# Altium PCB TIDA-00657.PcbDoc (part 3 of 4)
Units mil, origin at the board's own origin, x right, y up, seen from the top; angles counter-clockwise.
Board outline 2500 x 2500 mil, 4 copper layers (Top Layer, MidLayer1, MidLayer2, Bottom Layer); 149 components, 57 nets, 332 pads, 124 vias.
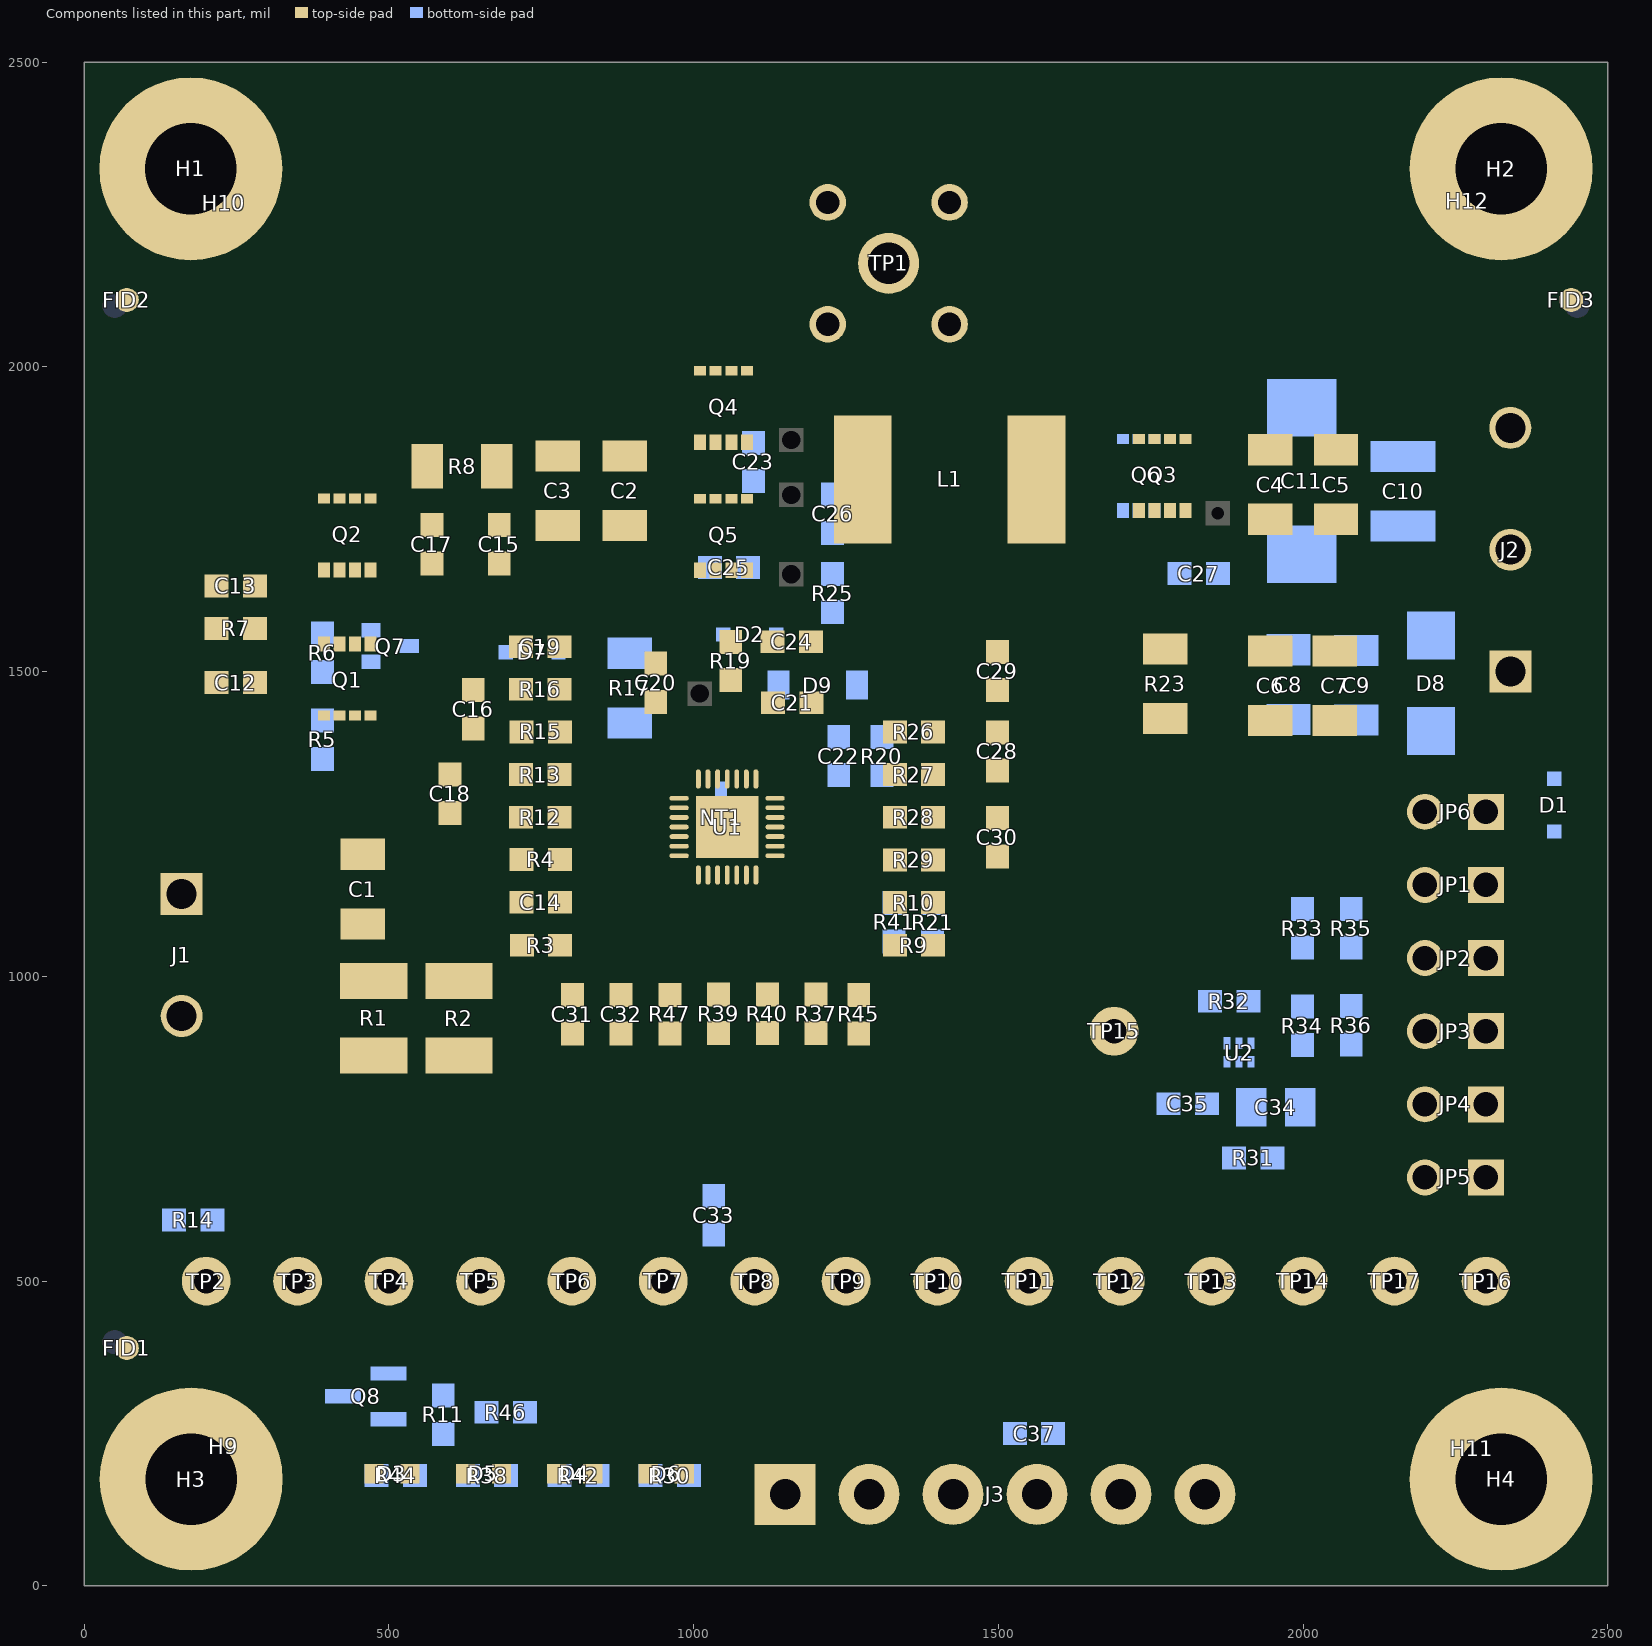
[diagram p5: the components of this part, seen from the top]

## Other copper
Top Layer:
  rectangle net PGND: 265,2148 284,2162
  rectangle net PGND: 283,2159 301,2172
  rectangle net PGND: 295,2156 312,2181
  rectangle net PGND: 278,2150 309,2164
  rectangle net PGND: 250,2140 311,2153
  rectangle net PGND: 312,2183 328,2199
  rectangle net PGND: 321,2181 336,2211
  rectangle net PGND: 332,2183 348,2225
  rectangle net PGND: 348,2234 359,2244
  rectangle net PGND: 352,2231 367,2265
  rectangle net PGND: 341,2160 383,2240
  rectangle net PGND: 305,2125 375,2188
  rectangle net NetC13_1: 454,1610 470,1626
  rectangle net NetC13_1: 443,1606 456,1633
  region net NetC13_1: 361,1570 385,1594 344,1635 320,1611
  region net NetQ1_4: 333,1539 346.5,1552.5 309,1590 295.5,1576.5
  region net BATSRC: 1281,1201 1290,1210 1270,1230 1261,1221
  region net BATSRC: 1275.5,1197.5 1282,1204 1259.5,1226.5 1253,1220
  region net BATSRC: 1279,1182 1287,1190 1247,1230 1239,1222
  region net BATSRC: 1275.5,1173.5 1283,1181 1235.5,1228.5 1228,1221
  region net BATDRV: 1256,1243 1268,1255 1262,1261 1250,1249
  region net BATDRV: 1245,1243 1266,1264 1261,1269 1240,1248
  region net BATDRV: 1237,1243 1267.5,1273.5 1260,1281 1229.5,1250.5
  region net SRN: 1290,1300 1306,1316 1292,1330 1276,1314
  region net SRN: 1272,1302 1305.5,1335.5 1295,1346 1261.5,1312.5
  region net GND: 1387,675 1434.5,722.5 1296,861 1248.5,813.5
  region net GND: 1517.14,751.14 1562,796 1515.86,842.14 1471,797.28
  region net GND: 1475.5,796.5 1556,877 1463.5,969.5 1383,889
  region net CMPOUT: 1350.5,930.5 1358,938 1343.5,952.5 1336,945
  region net CMPOUT: 1307,955 1319,967 1301,985 1289,973
  region net CMPOUT: 1269,991 1279,1001 1267,1013 1257,1003
  region net CMPOUT: 1201,1042 1210,1051 1191,1070 1182,1061
  region net CMPOUT: 1217,1040 1228,1051 1191,1088 1180,1077
  region net CMPOUT: 1154,1148 1160,1154 1153,1161 1147,1155
  region net CMPOUT: 1146.5,1131.5 1161,1146 1139.5,1167.5 1125,1153
  region net CMPOUT: 1241,1033 1264.5,1056.5 1160,1161 1136.5,1137.5
  region net SCL: 1118,997 1153,1032 1125,1060 1090,1025
  region net SCL: 1092,1065 1098.5,1071.5 1092,1078 1085.5,1071.5
  region net SCL: 1104,1038 1118.5,1052.5 1096,1075 1081.5,1060.5
  region net PMON: 986,1026 1008.5,1048.5 998,1059 975.5,1036.5
  region net PMON: 975,1031 1009,1065 998,1076 964,1042
  region net PMON: 952,1032 963,1043 957,1049 946,1038
  region net PMON: 963,1034 1008.5,1079.5 997,1091 951.5,1045.5
  region net IDCHG: 911,1018 929,1036 920,1045 902,1027
  region net IDCHG: 880,1016 893,1029 882,1040 869,1027
  region net IDCHG: 896,1018 957.5,1079.5 938,1099 876.5,1037.5
  region net IDCHG: 950,1077 979,1106 967,1118 938,1089
  region net IDCHG: 939,1081 976.5,1118.5 968,1127 930.5,1089.5
  region net VIN: 364.5,1125.5 377,1138 362.5,1152.5 350,1140
  region net PGND: 385,890 407,912 369,950 347,928
  region net NetC1_2: 410.5,941.5 425,956 405.5,975.5 391,961
  region net NetC1_2: 653,967 687.5,1001.5 574,1115 539.5,1080.5
  region net GND: 675.5,1097.5 710,1132 654.5,1187.5 620,1153
  region net GND: 624,1151 672,1199 620,1251 572,1203
  region net VIN: 570,1137 578.5,1145.5 572,1152 563.5,1143.5
  region net VIN: 557,1137 572,1152 565,1159 550,1144
  region net VIN: 549,1140 565.5,1156.5 551,1171 534.5,1154.5
  region net VIN: 694.5,1049.5 704,1059 683.5,1079.5 674,1070
  region net VIN: 691.28,1027 705.14,1040.86 549,1197 535.14,1183.14
  region net ACDET: 765,1023 778,1036 770,1044 757,1031
  region net ACDET: 722.5,956.5 731,965 718.5,977.5 710,969
  region net ACDET: 728,966 795,1033 783,1045 716,978
  region net IADP: 758,936 819,997 808,1008 747,947
  region net IADP: 827,997 849,1019 837,1031 815,1009
  region net IADP: 815,1002 846,1033 841,1038 810,1007
  region net IADP: 824.14,1025.86 832.28,1034 821.14,1045.14 813,1037
  region net IADP: 834.36,1031.36 836,1033 833.64,1035.36 832,1033.72
  region net IADP: 829,1033 831,1035 818,1048 816,1046
  region net IADP: 830.14,1031.86 959,1160.72 944.86,1174.86 816,1046
  region net ACDET: 798.5,1085.5 820,1107 803.5,1123.5 782,1102
  region net ACDET: 853,1162 858,1167 849,1176 844,1171
  region net ACDET: 852.5,1139.5 877,1164 862.5,1178.5 838,1154
  region net ACDET: 801.5,1063.5 897,1159 878.5,1177.5 783,1082
  region net IADP: 955,1161 979,1185 967,1197 943,1173
  region net ACDET: 892,1159 943,1210 936,1217 885,1166
  region net ACDET: 896,1155 950,1209 944,1215 890,1161
  region net ACOK: 880,1202 901,1223 894,1230 873,1209
  region net ACOK: 879.5,1193.5 911,1225 904.5,1231.5 873,1200
  region net ACDRV: 873,1241 883.5,1251.5 867,1268 856.5,1257.5
  region net ACDRV: 890,1243 898,1251 867,1282 859,1274
  region net CMSRC: 863,1306 869.5,1312.5 859,1323 852.5,1316.5
  region net CMSRC: 847,1308 863.22,1324.22 847,1340.43 830.78,1324.22
  region net ACP: 870,1365 877,1372 871,1378 864,1371
  region net ACP: 863.5,1367.5 876,1380 870.5,1385.5 858,1373
  region net ACP: 860,1373 876,1389 838,1427 822,1411
  region net NetC16_1: 622,1348 649,1375 628,1396 601,1369
  region net NetC16_1: 601,1410 617.5,1426.5 597,1447 580.5,1430.5
  region net SYS: 645,1555 654.5,1564.5 640,1579 630.5,1569.5
  region net NetC16_1: 602.5,1505.5 610,1513 600.5,1522.5 593,1515
  region net NetC16_1: 610,1510 614,1514 600,1528 596,1524
  region net NetC16_1: 585.5,1486.5 609,1510 592.5,1526.5 569,1503
  region net NetC16_1: 571,1489 612.5,1530.5 605,1538 563.5,1496.5
  region net ACN: 894.5,1405.5 902,1413 896.5,1418.5 889,1411
  region net ACN: 888,1408 903,1423 895,1431 880,1416
  region net ACN: 881.5,1413.5 900,1432 885.5,1446.5 867,1428
  region net ACN: 871,1428 897.5,1454.5 859,1493 832.5,1466.5
  region net ACN: 969.5,1289.5 976,1296 907.5,1364.5 901,1358
  region net VCC: 949.5,1359.5 960,1370 947.5,1382.5 937,1372
  region net VCC: 942,1370 955,1383 940,1398 927,1385
  region net PHASE: 1002.5,1351.5 1012,1361 983.5,1389.5 974,1380
  region net VCC: 953.5,1399.5 974,1420 956.5,1437.5 936,1417
  region net HIDRV: 1030,1390 1039,1399 1030,1408 1021,1399
  region net HIDRV: 1034.5,1389.5 1040,1395 1031.5,1403.5 1026,1398
  region net HIDRV: 1024,1397 1042,1415 1033,1424 1015,1406
  region net LODRV: 1093,1363 1118.5,1388.5 1110,1397 1084.5,1371.5
  region net REGN: 1081,1393 1111,1423 1100,1434 1070,1404
  region net BTST: 1059.61,1424.39 1080.22,1445 1061.61,1463.61 1041,1443
  region net PGND: 961,1562 992,1593 973,1612 942,1581
  region net PGND: 883.5,1536.5 905,1558 878.5,1584.5 857,1563
  region net PGND: 827,1573 883,1629 789,1723 733,1667
  region net PGND: 966,1664 984,1682 964,1702 946,1684
  region net SYS: 903.5,1786.5 963,1846 929.5,1879.5 870,1820
  region net SYS: 950.86,1872.14 992,1913.28 962.14,1943.14 921,1902
  region net PHASE: 1194,1816 1214.5,1836.5 1196,1855 1175.5,1834.5
  region net PGND: 1288.36,1436.64 1294,1442.28 1277.64,1458.64 1272,1453
  region net PGND: 1248,1492 1257,1501 1245,1513 1236,1504
  region net PGND: 1255,1574 1272.14,1591.14 1259.28,1604 1242.14,1586.86
  region net PHASE: 1244.5,1684.5 1264,1704 1248.5,1719.5 1229,1700
  region net PGND: 1356,1663 1397.5,1704.5 1379,1723 1337.5,1681.5
  region net PHASE: 1325.5,1707.5 1353,1735 1327.5,1760.5 1300,1733
  region net BAT: 1883,1426 1912.5,1455.5 1894,1474 1864.5,1444.5
  region net BAT: 1479.5,1284.5 1495,1300 1476.5,1318.5 1461,1303
  region net BAT: 1612,1242 1736.5,1366.5 1669,1434 1544.5,1309.5
  region net BAT: 1529,1338 1545,1354 1535,1364 1519,1348
  region net BAT: 1525,1323 1667,1465 1658,1474 1516,1332
  region net NetC27_2: 1529.5,1420.5 1548,1439 1537.5,1449.5 1519,1431
  region net NetC27_2: 1523,1396 1566,1439 1555,1450 1512,1407
  region net NetC27_2: 1531,1383 1637,1489 1628,1498 1522,1392
  region net NetC27_2: 1773,1489 1782,1498 1776,1504 1767,1495
  region net GND: 1571.5,1472.5 1610,1511 1587.5,1533.5 1549,1495
  region net GND: 1600,1527 1617.5,1544.5 1599,1563 1581.5,1545.5
  region net NetC27_2: 1627.5,1557.5 1646,1576 1615.5,1606.5 1597,1588
  region net NetC27_2: 1628.5,1810.5 1651,1833 1631.5,1852.5 1609,1830
  region net NetC27_2: 1638,1887 1655.5,1904.5 1635,1925 1617.5,1907.5
  region net PGND: 1460.5,1927.5 1479,1946 1461.5,1963.5 1443,1945
  region net PGND: 1200,2041 1218,2059 1185,2092 1167,2074
  region net PGND: 1253,1999 1292,2038 1273,2057 1234,2018
  region net PHASE: 1283,1982 1327,2026 1319,2034 1275,1990
  region net PGND: 1327,1956 1365.5,1994.5 1344,2016 1305.5,1977.5
  region net PGND: 1365,2086 1402,2123 1383,2142 1346,2105
  region net PGND: 1268,2088 1291,2111 1258,2144 1235,2121
  region net PGND: 1250,2187 1297,2234 1265,2266 1218,2219
  region net PGND: 1386,2190 1420,2224 1378,2266 1344,2232
  region net PGND: 2140,2220 2159.5,2239.5 2147,2252 2127.5,2232.5
  region net PGND: 2127,2231 2152,2256 2141,2267 2116,2242
  region net PGND: 2166.5,2203.5 2175,2212 2134.5,2252.5 2126,2244
  region net PGND: 2153.5,2168.5 2182,2197 2132.5,2246.5 2104,2218
  region net PGND: 2194,2154 2210.5,2170.5 2184,2197 2167.5,2180.5
  region net PGND: 1624.5,2105.5 1673,2154 1641.5,2185.5 1593,2137
  region net SYS: 1667,2073 1704,2110 1682,2132 1645,2095
  rectangle net SYS: 1685,1932 1745,2135
  rectangle net SYS: 1728,1800 2361,2135
  region net SYS: 1685,1904 1713,1932 1676,1969 1648,1941
  region net PGND: 2135.5,1499.5 2223,1587 2147.5,1662.5 2060,1575
  region net BAT: 2183,1423 2278,1518 2233,1563 2138,1468
  region net BAT: 2236.5,1302.5 2261,1327 2245.5,1342.5 2221,1318
  region net BAT: 2263,1163 2289,1189 2220,1258 2194,1232
  region net GND: 371.5,222.5 388,239 366.5,260.5 350,244
  region net GND: 375.5,227.5 382,234 352.5,263.5 346,257
  region net GND: 371.5,238.5 386,253 352.5,286.5 338,272
  region net GND: 364.5,252.5 388,276 345.5,318.5 322,295
  region net GND: 329,292 353,316 329,340 305,316
  region net GND: 301.5,316.5 316,331 300.5,346.5 286,332
  region net GND: 284.5,325.5 309,350 288.5,370.5 264,346
  region net GND: 260.5,340.5 284,364 270.5,377.5 247,354
  region net GND: 244,347 265,368 255,378 234,357
  region net ACDET: 615,561 623,569 617,575 609,567
  region net ACDET: 545.5,493.5 551,499 543.5,506.5 538,501
  region net ACDET: 687,562 727,602 721,608 681,568
  region net IADP: 796,507 805,516 752,569 743,560
  region net GND: 1012,520 1033,541 980,594 959,573
  region net CMPIN: 1458,454 1468,464 1463,469 1453,459
  region net GND: 1311,591 1338,618 1279,677 1252,650
  region net SCL: 1190,567 1197,574 1161,610 1154,603
  region net SDA: 1077,625 1085,633 1082,636 1074,628
  region net GND: 1103.5,550.5 1113,560 1049.5,623.5 1040,614
  region net SDA: 1284,229 1294.5,239.5 1163,371 1152.5,360.5
  region net GND: 1311,286 1356,331 1310,377 1265,332
  region net SCL: 1410.28,150 1418.14,157.86 1193,383 1185.14,375.14
  rectangle net SDA: 1287,162 1302,230
  rectangle net CMPOUT: 1800,165 1843,195
  rectangle net CMPIN: 1703,211 1710,218
  rectangle net CMPIN: 1700,160 1713.72,216
  region net 3V3: 1556.5,155.5 1585,184 1336.5,432.5 1308,404
  rectangle net 3V3: 1309,404 1345,520
  region net 3V3: 1324.5,503.5 1346.5,525.5 1278,594 1256,572
  region net 3V3: 1249,562 1277.5,590.5 1271,597 1242.5,568.5
  region net 3V3: 1236,562 1271,597 1224,644 1189,609
  region net CMPOUT: 1823,135 1851,163 1824,190 1796,162
  region net CMPOUT: 1816,154 1827,165 1796,196 1785,185
  region net GND: 2131.5,227.5 2154,250 2144.5,259.5 2122,237
  region net GND: 2133,239 2162,268 2147,283 2118,254
  region net GND: 2132,248 2169,285 2161,293 2124,256
  region net GND: 2213,324 2232,343 2211,364 2192,345
  region net GND: 2235,337 2252,354 2230,376 2213,359
  region net GND: 2255,348 2268,361 2249,380 2236,367
  region net GND: 2195,317 2238,360 2218,380 2175,337
  region net GND: 2116,237 2200,321 2161,360 2077,276
  region net GND: 2132,275 2227,370 2190,407 2095,312
  rectangle net PGND: 2129,2167 2183,2201
  rectangle net PGND: 2119,2157 2214,2173
  rectangle net PGND: 1344,1967 1395,2110
  rectangle net PGND: 1382,1947 1625,2157
  rectangle net PGND: 1383,2155 2132,2256
  rectangle net PGND: 1163,2234 2135,2473
  rectangle net SYS: 1645,1942 1707,2096
  rectangle net SYS: 2275,1800 2457,2035
  rectangle net SYS: 1684,1823 1699,1835
  rectangle net SYS: 1676,1833 1698,1840
  rectangle net SYS: 1693,1802 1743,1848
  rectangle net SYS: 1676,1839 1757,1938
  rectangle net NetC27_2: 1611,1836 1654,1906
  rectangle net NetC27_2: 1636,1769 1650,1780
  rectangle net NetC27_2: 1626,1766 1638,1787
  rectangle net NetC27_2: 1620,1751 1685,1772
  rectangle net NetC27_2: 1588,1715 1790,1756
  rectangle net NetC27_1: 1806,1744 1889,1780
  rectangle net NetC27_2: 1677,1748 1785,1778
  rectangle net NetC27_2: 1598,1608 1883,1722
  rectangle net NetC27_2: 1632,1515 1885,1609
  rectangle net NetC27_2: 1485,1590 1633,1923
  rectangle net GND: 1577,1514 1614,1544
  rectangle net GND: 1540,1503 1546,1511
  rectangle net GND: 1544,1469 1574,1516
  rectangle net PGND: 1450,1555 1461.41,1561
  rectangle net GND: 1479,1509 1494,1544
  rectangle net GND: 1485,1508 1596,1565
  rectangle net PGND: 1245,1445 1456,1589.72
  rectangle net NetC27_2: 1468,1420 1479,1429
  rectangle net NetC27_2: 1473,1413 1524,1490
  rectangle net NetC27_2: 1372,1381 1528,1425
  rectangle net BAT: 1475,1236 1527,1312
  rectangle net BAT: 1369,1305 1528,1361
  rectangle net NetC27_1: 1371,1235 1454,1282
  rectangle net SRN: 1294,1305 1352,1348
  rectangle net GND: 1257,1383 1270,1394
  rectangle net GND: 1258,1392 1280,1404
  rectangle net GND: 1237,1372 1261,1404
  rectangle net SRP: 1296,1371 1311,1383
  rectangle net SRP: 1303,1372 1350,1424
  rectangle net PGND: 1170,1427 1285,1506
  rectangle net PGND: 1169,1482 1199,1507
  rectangle net PGND: 1377,1677 1465,1969
  rectangle net PHASE: 1229,1704 1324,1754
  rectangle net PGND: 1268,1558.59 1465,1685
  rectangle net PHASE: 1180,1605 1191,1612
  rectangle net PHASE: 1186,1605 1238,1623
  rectangle net PHASE: 1196,1615 1244,1714
  rectangle net PHASE: 1176,1525 1226,1608
  rectangle net PHASE: 1196,1737 1353,1924
  rectangle net PHASE: 986,1708 1250,1844
  rectangle net PHASE: 986,1840 1068,1882
  rectangle net PHASE: 994,1851 1015,1889
  rectangle net PHASE: 1002,1855 1066,1893
  rectangle net HIDRV: 1143,1869 1155,1888
  rectangle net HIDRV: 1085,1867 1145,1894
  rectangle net BAT: 1545,1235 1684,1314
  rectangle net BAT: 1680,1235 1898,1443
  rectangle net BAT: 1894,1234 2246,1476
  rectangle net PGND: 1904,1496 2139,1590
  rectangle net PGND: 1904,1585 2455,1779
  rectangle net BAT: 2231,1328 2453,1565
  rectangle net BAT: 2257,1117 2345,1215
  rectangle net GND: 2366,1197 2456,1255
  rectangle net ILIM: 1371,1100 1455,1149
  rectangle net NetC27_2: 1371,1167 1454,1215
  rectangle net GND: 1476,1173 1519,1215
  rectangle net GND: 1379,890 1527,936
  rectangle net GND: 1370,1034 1415,1072
  rectangle net GND: 1539,1137 1557,1152
  rectangle net GND: 1544,993 1654,1217
  rectangle net GND: 1517,734 1672,1016
  rectangle net GND: 1517,589 1656,748
  rectangle net GND: 1642,597 2115,1216
  rectangle net GND: 1275,628 1381,772
  rectangle net GND: 1304,599 1433,722
  rectangle net GND: 1246,652 1293,863
  rectangle net 3V3: 1185,611 1229,929
  rectangle net CMPIN: 1244,887 1325,929
  rectangle net CMPOUT: 1291,950 1354,965
  rectangle net CMPOUT: 1246,950 1296,1005
  rectangle net CMPOUT: 1185,951 1265,1054
  rectangle net SCL: 1102,1011 1162,1031
  rectangle net SCL: 1086,1026 1137,1055
  rectangle net SCL: 1149,954 1165,976
  rectangle net SCL: 1106,974 1166,1022
  rectangle net \BATPRES: 1315,998 1332,1024
  rectangle net \BATPRES: 1326,987 1350,1028
  rectangle net \BATPRES: 1286,1026 1352,1081
  rectangle net \TB_STAT: 1271,1119 1298,1150
  rectangle net \TB_STAT: 1289,1103 1349,1148
  rectangle net BATSRC: 1275,1172 1350,1225
  rectangle net BATDRV: 1261,1245 1348,1285
  rectangle net GND: 1235,1361 1249,1402
  rectangle net GND: 1127,1344 1148,1354
  rectangle net GND: 1140,1346 1170,1365
  rectangle net GND: 1146,1355 1240,1405.06
  rectangle net REGN: 1105,1425 1149.94,1504
  rectangle net PGND: 824,1563 894,1598
  rectangle net GND: 760,1515 805,1566.72
  rectangle net LODRV: 1086,1637 1175,1683
  rectangle net NetC24_1: 999,1525 1154,1565
  rectangle net PGND: 1054,1585 1152,1615
  rectangle net PGND: 803,1598 1064,1685
  rectangle net PGND: 876,1500 904,1597
  rectangle net PGND: 895,1497 973,1596
  rectangle net BTST: 996,1445 1085,1504
  rectangle net VCC: 923,1384 953,1426
  rectangle net VCC: 919,1421 975,1474
  rectangle net ACOK: 864,1194 883,1222
  rectangle net ACP: 831,1376 866,1404
  rectangle net ACN: 863,1433 899,1454
  rectangle net ACN: 760,1451 856,1494
  rectangle net SYS: 618,1453 639,1496
  rectangle net SYS: 630,1450 739,1563
  rectangle net PGND: 730.17,1669 963,1764.83
  rectangle net SYS: 637,1826 658,1845
  rectangle net VIN: 250,1434 263,1447
  rectangle net NetQ1_4: 298,1553 330,1571
  rectangle net NetQ1_4: 291,1531 401,1556
  rectangle net NetQ1_4: 258,1529 308,1594
  rectangle net NetC13_1: 351,1576.28 472,1615
  rectangle net NetC13_1: 258,1612 449,1685
  rectangle net NetC12_2: 484,1634 497,1645
  rectangle net NetC12_2: 472,1643 496,1655
  rectangle net NetC12_2: 492,1628.18 527,1656
  rectangle net NetC12_2: 467,1653.18 530,1684
  rectangle net NetC13_1: 416,1530 529,1605
  rectangle net GND: 562,1544 578,1559
  rectangle net GND: 552,1533 566,1558
  rectangle net GND: 550,1556 585,1697
  rectangle net NetC16_1: 559,1749 596,1763
  rectangle net NetC16_1: 551,1720 601,1756
  rectangle net NetC16_1: 587,1825 605,1843
  rectangle net NetC16_1: 515,1785 583,1914
  rectangle net NetC16_1: 260.16,1705 530,1914.84
  rectangle net ACDRV: 761,1237 867,1288
  rectangle net CMSRC: 761,1311 844,1352
  rectangle net NetC13_1: 649,1309 667,1349
  rectangle net NetC13_1: 658,1308 736,1352
  rectangle net ACP: 760,1373 836,1430
  rectangle net NetC16_1: 614,1375 740,1430
  rectangle net NetC16_1: 590,1311 625,1432
  rectangle net NetC16_1: 563,1309 597,1497
  rectangle net GND: 614,1157 681,1221
  rectangle net VIN: 692,1028 738,1073
  rectangle net IADP: 808,978 845,1014
  rectangle net IADP: 784,949 843,987
  rectangle net IDCHG: 912,940 924,952
  rectangle net IDCHG: 864,950 928,1029
  rectangle net PMON: 990,937 1006,951
  rectangle net PMON: 945,950 1005,1042
  rectangle net SDA: 1042,1060 1053,1070
  rectangle net SDA: 1058,1059 1063,1080
  rectangle net SDA: 1032,1048 1064,1062
  rectangle net SDA: 1027,995 1066,1052
  rectangle net SDA: 1073,941 1082,952
  rectangle net SDA: 1025,950 1084,995
  rectangle net 3V3: 1105,847 1133,933
  rectangle net 3V3: 1027,845 1055,930
  rectangle net GND: 1032,613 1057,627
  rectangle net GND: 1122,620 1133,629
  rectangle net GND: 1114,627 1135,640
  rectangle net GND: 1105,638 1135,821
  rectangle net GND: 1025,623 1054,822
  rectangle net IDCHG: 943,504 956,527
  rectangle net IDCHG: 935,508 946,536
  rectangle net IDCHG: 928,519 938,544
  rectangle net GND: 947,557 978,928
  rectangle net GND: 831,540 853,554
  rectangle net GND: 787,559 801,570
  rectangle net GND: 796,553 867,572
  rectangle net GND: 844,538 895,576
  rectangle net GND: 778,568 895,927
  rectangle net GND: 270,338 312,366
  rectangle net GND: 338,273 368,324
  rectangle net GND: 301,317 373,368
  rectangle net GND: 388,351 477,425
  rectangle net GND: 159,370 238,434
  rectangle net \TB_STAT: 965,165 1004,243
  rectangle net NetD6_1: 908,125 943,206
  rectangle net \BATPRES: 815,165 855,243
  rectangle net NetD4_1: 753,128 794,203
  rectangle net \PROCHOT: 666,168 705,246
  rectangle net NetD5_1: 604,126 645,206
  rectangle net NetD3_2: 519,165 553,245
  rectangle net NetD3_1: 456,131 500,205
  rectangle net ACDET: 758,1036 797,1110
  rectangle net ACDET: 761,1108 847,1220
  rectangle net NetC12_2: 654,1242 740,1255
  rectangle net NetC12_2: 645,1250 742,1289
  rectangle net GND: 565,1204 628,1290
  rectangle net GND: 676,1097 740,1219
  rectangle net NetC1_2: 537,999 641,1049
  rectangle net NetC1_2: 402.28,945 693,1005
  rectangle net NetC1_2: 388,960 572,1119
  rectangle net VIN: 338,1140 543,1352
  rectangle net VIN: 258,1343 544,1510
  rectangle net VIN: 46,1056 365,1438
  rectangle net PGND: 679,608 692,619
  rectangle net PGND: 670,601 683,619
  rectangle net PGND: 593,590 600,599
  rectangle net PGND: 581,581 596,597
  rectangle net PGND: 565,569 585,599
  rectangle net PGND: 564,596.28 676,623
  rectangle net PGND: 309,617 696,921
  rectangle net PGND: 45,566 573,709
  rectangle net PGND: 44,708 366,1034
  rectangle net PGND: 1209,2097 1257,2248
  rectangle net PGND: 1305,1943 1386,1980
  rectangle net PGND: 1217,2037 1293,2111
  rectangle net PGND: 1193,1946 1256,2090
  rectangle net PGND: 626,2068 641,2078
  rectangle net PGND: 365,2074 1225,2474
  rectangle net PGND: 234,1928 246,1939
  rectangle net PGND: 236,1934 634,1937
  rectangle net PGND: 233,1934 634,2146
  rectangle net PGND: 163,1719 174,1727
  rectangle net PGND: 146,1725 240,2133
  rectangle net NetC12_2: 185,1460 238,1705
  rectangle net PGND: 43,1461 167,2036
  rectangle net SYS: 895,1844 964,1924
  rectangle net SYS: 1153,2035 1167,2047
  rectangle net SYS: 1140,1917 1173,2031
  rectangle net SYS: 889,1913 1156,2057
  rectangle net SYS: 658,1784 906,2056
  rectangle net GND: 2167,365 2455,405
  rectangle net GND: 1475,1068 1605,1145
  rectangle net GND: 1441,1003 1629,1077
  rectangle net GND: 1378,926 1531,1010
  rectangle net SYS: 658,1720 710,1785
  rectangle net PGND: 653,1657 745,1703
  rectangle net GND: 654,1591 738,1638
  rectangle net GND: 662,1579 778,1595
  rectangle net GND: 759,1563 786,1587
  rectangle net GND: 784,1563 795,1581
  rectangle net GND: 793,1564 798,1571
  rectangle net GND: 730,1588 746,1628
  rectangle net GND: 744,1588 756,1619
  rectangle net GND: 754,1586 762,1611
  rectangle net GND: 761,1591 771,1604
  text "Top Layer" at 577,-858.49 h60
MidLayer1:
  text "MidLayer1" at 577,-858.49 h60
MidLayer2:
  rectangle net GND: 993,1177 1123,1307
  text "MidLayer2" at 577,-858.49 h60
Bottom Layer:
  rectangle net GND: 367,46 500,110
  rectangle net GND: 254,441 297,522
  rectangle net GND: 96,365 429,448
  rectangle: 318,376 353,394
  rectangle net GND: 97,443 146,447
  rectangle net GND: 44,443 146,548
  rectangle net GND: 43,544 170,653
  rectangle net GND: 523,738 652,765
  rectangle net GND: 45,636 551,765
  rectangle net BAT: 1906,1315 2378,1475.11
  rectangle net BAT: 2290,1357 2457,1535
  rectangle net BAT: 2376,1349 2385,1359
  rectangle net BAT: 2280,1471 2297,1526
  rectangle net BAT: 2268,1460 2291,1516
  rectangle net BAT: 2260,1460 2282,1504
  rectangle net BAT: 2252,1464 2269,1496
  rectangle net BAT: 2240,1469 2258,1487
  rectangle net NetD1_1: 2395,1277 2453,1335
  rectangle net NetD1_2: 2273,1225 2376,1298
  rectangle net NetD1_2: 2363,1225 2425,1255
  rectangle net NetD1_2: 2374,1248 2385,1259
  rectangle net GND: 2332,1195 2345.12,1204
  rectangle net GND: 2346,368 2454.88,1205
  rectangle net GND: 2276,954.53 2344,985
  rectangle net GND: 2276,1072 2349,1107
  rectangle net GND: 2278,845 2349,865
  rectangle net \BATPRES: 2275,797 2306,824
  rectangle net \BATPRES: 2275,612 2325,821
  rectangle net \BATPRES: 1814,564.7 2274.7,585
  rectangle net \BATPRES: 2275,601 2317,614
  rectangle net \BATPRES: 2270.7,579 2294,603.42
  rectangle net \BATPRES: 2293,591 2306,603
  rectangle net \BATPRES: 2259,570 2284,597
  rectangle net 3V3: 1025,847 1227,885
  rectangle net \TB_STAT: 1272,1108 1348,1155
  rectangle net 3V3: 1288,1041 1408,1080
  rectangle net 3V3: 1286,1015 1298,1046
  rectangle net 3V3: 1296,1029 1309,1043
  rectangle net GND: 433,107 446,114
  rectangle net NetD3_1: 453,130 500,197
  rectangle net 3V3: 522,47 587,195
  rectangle net NetD5_1: 607,134 646,196
  rectangle net ACOK: 566,293 611,306
  rectangle net 3V3: 571,223 641,271
  rectangle net 3V3: 634,265 674,304
  rectangle net 3V3: 629,261 642,278
  rectangle net 3V3: 568,215 604,228
  rectangle net 3V3: 569,206 595,217
  rectangle net 3V3: 557,193 585,210
  rectangle net 3V3: 668,112 735,200
  rectangle net 3V3: 584,45 1018,108
  rectangle net 3V3: 1013,45 1627,74
  rectangle net GND: 1569,226 1627,272
  rectangle net 3V3: 1505,202 1553,270
  rectangle net 3V3: 1507,63 1625,205
  rectangle net 3V3: 1497,58 1525,96
  rectangle net 3V3: 1488,61 1510,88
  rectangle net 3V3: 1481,65 1496,81
  rectangle net 3V3: 970,96 1013,186
  rectangle net 3V3: 1014,75 1024,96
  rectangle net 3V3: 1023,71 1036,88
  rectangle net 3V3: 962,100 977,115
  rectangle net NetD6_1: 903,132 948,202
  rectangle net 3V3: 818,106 885,200
  rectangle net NetD4_1: 754,130 801,201
  rectangle net \PROCHOT: 700,219 746,304
  rectangle net \PROCHOT: 662,219 708,246
  rectangle net \PROCHOT: 689,238 709,257
  rectangle net ACOK: 603,452 684,550
  rectangle net ACOK: 662,539 683,606
  rectangle net ACOK: 642,538 674,586
  rectangle net ACOK: 624,539 655,569
  rectangle net ACOK: 608,441 676,456
  rectangle net ACOK: 606,429 665,443
  rectangle net ACOK: 605,399.01 629.01,437
  rectangle net ACOK: 624,418 653,431
  rectangle net ACOK: 625,406 642,421
  rectangle net SYS: 1647,1844 2279,2054
  rectangle net SYS: 1771,1807 2387,1950
  rectangle net SYS: 1695,1800 1828,1810
  rectangle net PGND: 1907,1497 2227,1783
  rectangle net PGND: 2181,1555 2455,1783
  rectangle net 3V3: 971,178 1012,197
  rectangle net 3V3: 583,101 598,122
  rectangle net 3V3: 594,100 609,111
  rectangle net 3V3: 552,186 565,204
  rectangle net NetD3_2: 541,221 547,230
  rectangle net 3V3: 666,271 680,303
  rectangle net GND: 553,441 582,543
  rectangle net GND: 548,528 558,542
  rectangle net GND: 455,380 523.72,444
  rectangle net GND: 518,412 557,446
  rectangle net GND: 545,434 582,470
  rectangle net ACOK: 567,357 614,396
  rectangle net GND: 403.91,453 445,526.56
  rectangle net GND: 421,524 451,544
  rectangle net GND: 410,521 426,537
  rectangle net CMSRC: 191,548 253,612
  rectangle net GND: 539,689 602,742
  rectangle net NetC12_2: 185,1646 481,1704
  rectangle net NetC13_1: 365,1544 458,1621
  rectangle net NetC13_1: 442,1543 484,1594
  rectangle net NetC13_1: 455,1586 467,1616
  rectangle net NetC13_1: 465,1588 475,1608
  rectangle net NetC13_1: 473,1589 481,1601
  rectangle net NetQ7_1: 366,1494 485,1524.93
  rectangle net NetQ7_1: 367,1401 425,1500
  rectangle net PGND: 367,1334 427,1380
  rectangle net PGND: 455,1461 475,1473
  rectangle net PGND: 446,1417 477,1466
  rectangle net VIN: 495.93,1436 534,1477.64
  rectangle net VIN: 503,1453 539,1491
  rectangle net VIN: 517,1466 556,1510
  rectangle net VIN: 534,1458 549,1473
  rectangle net VIN: 569,1505 706,1545
  rectangle net VIN: 563,1499.34 586.34,1516
  rectangle net VIN: 554,1492 581,1511
  rectangle net VIN: 554,1474 565,1494
  rectangle net VIN: 561,1484 575,1494
  rectangle net NetC12_2: 505,1530 550,1576
  rectangle net NetC12_2: 505,1567 535,1650
  rectangle net NetC12_2: 533,1572 544,1582
  rectangle net NetC12_2: 473,1632 532,1654
  rectangle net NetD1_1: 765,1506 935,1564
  rectangle net NetC24_1: 1007,1536 1054,1575
  rectangle net VCC: 858,1398 950,1445
  rectangle net NetC27_1: 1847,1500 1888,1783
  rectangle net NetC27_2: 1647,1691 1790,1735
  rectangle net NetC27_2: 1723,1704 1791,1780
  rectangle net NetC27_2: 1702,1637 1791,1704
  rectangle net NetC27_2: 1675,1661 1717,1695
  rectangle net NetC27_1: 1645,1757 1676,1823
  rectangle net NetC27_1: 1672,1756 1711,1778
  rectangle net NetC27_1: 1427,1245 1629,1275
  rectangle net GND: 1147,1371 1328,1436
  rectangle net GND: 1127,1335.82 1155.82,1353
  rectangle net GND: 1145,1363 1187,1375
  rectangle net GND: 1145,1355 1178,1367
  rectangle net GND: 1137,1340 1164,1362
  rectangle net GND: 1159,1349 1171,1356
  rectangle net ILIM: 1200,1305 1361,1352
  rectangle net ILIM: 1190,1307 1214,1346
  rectangle net ILIM: 1181,1306 1204,1335
  rectangle net ILIM: 1171,1307 1190,1328
  rectangle net ILIM: 1358,1301 1372,1343
  rectangle net ILIM: 1370,1103 1404,1304
  rectangle net ILIM: 1394,1102 1455,1154
  rectangle net 3V3: 1381,1043 1417,1080
  rectangle net ILIM: 1401,1148 1416,1162
  rectangle net NetR32_1: 1826,888 1872,982
  rectangle net SYS: 695,1907 968,2047
  rectangle net SYS: 943,1921 985,2041
  rectangle net SYS: 962,1912 977,1924
  rectangle net HIDRV: 1070,1855 1184,1904
  rectangle net PHASE: 1072,1781 1247,1836
  rectangle net PHASE: 1137,1767 1249,1783
  rectangle net PHASE: 1128,1772 1144,1782
  rectangle net PGND: 1001,1656 1049,1760
  rectangle net LODRV: 1076,1648 1082,1657
  rectangle net LODRV: 1086,1585 1116,1599
  rectangle net LODRV: 1084,1534 1106,1592
  rectangle net LODRV: 1087,1525 1099,1538
  rectangle net REGN: 1126.5,1455 1152,1573.22
  rectangle net REGN: 1119,1458 1130,1524
  rectangle net PGND: 1179,1453 1371,1575
  rectangle net PGND: 1206,1564 1313,1617
  rectangle net NetC26_2: 1206,1641 1249,1744
  rectangle net LODRV: 1077,1369 1125,1434
  rectangle net LODRV: 1087,1429 1097,1451
  rectangle net LODRV: 1096,1429 1105,1443
  region net NetC12_2: 498,1612 534.5,1648.5 481,1702 444.5,1665.5
  region net NetC12_2: 507,1602 517,1612 505,1624 495,1614
  region net NetQ7_1: 415,1460 447,1492 431,1508 399,1476
  region net ILIM: 1381,1279 1406,1304 1372.46,1337.54 1347.46,1312.54
  region net GND: 551.5,639.5 648,736 616.5,767.5 520,671
  region net CMSRC: 256,560 301,605 288,618 243,573
  region net CMSRC: 253,580 281,608 271,618 243,590
  region net CMSRC: 251.5,594.5 266,609 257.5,617.5 243,603
  region net CMSRC: 276.5,597.5 289,610 281.5,617.5 269,605
  region net CMSRC: 197,508 238,549 225,562 184,521
  region net CMSRC: 196,526 216,546 207,555 187,535
  region net CMSRC: 194.5,538.5 203,547 196.5,553.5 188,545
  region net GND: 138.75,516.25 166.56,544.05 153.81,556.81 126,529
  region net GND: 162,427 179,444 146,477 129,460
  region net GND: 242,429 270.72,457.72 253.25,475.18 224.54,446.46
  region net GND: 307,429 325.14,447.14 299.03,473.25 280.89,455.11
  region net GND: 384,433 417.5,466.5 404,480 370.5,446.5
  region net GND: 470,425 483.5,438.5 447,475 433.5,461.5
  region net GND: 245.5,347.5 276,378 263.5,390.5 233,360
  region net GND: 262.5,339.5 287,364 272.5,378.5 248,354
  region net GND: 339.5,272.5 381.5,314.5 307,389 265,347
  region net GND: 375,230 385,240 353,272 343,262
  region net GND: 371,226 385,240 362,263 348,249
  region net GND: 526,384 578,436 556,458 504,406
  region net GND: 532,424 562.5,454.5 550,467 519.5,436.5
  region net ACOK: 556,329 633.5,406.5 608,432 530.5,354.5
  region net GND: 274,503 338,567 322,583 258,519
  region net GND: 357,552 386,581 377,590 348,561
  region net GND: 2306,504 2375.5,573.5 2345,604 2275.5,534.5
  region net NetC35_2: 2238.5,600.5 2255,617 2240.5,631.5 2224,615
  region net NetC35_2: 2244,617 2259,632 2248,643 2233,628
  region net NetC27_1: 1630,1246 1885,1501 1865,1521 1610,1266
  region net PGND: 2224.5,1497.5 2285,1558 2244.5,1598.5 2184,1538
  region net SYS: 2326,1885 2388.5,1947.5 2283,2053 2220.5,1990.5
  rectangle net GND: 319.95,556 369,583.95
  rectangle net PGND: 332,1293 469,1367
  rectangle net PGND: 405,785 655,857
  rectangle net PGND: 728,1653 994,1720
  rectangle net PGND: 819,1592 1002,1654
  rectangle net PGND: 985,1597 1052,1653
  rectangle net PGND: 1040,1607 1066,1633
  rectangle net PGND: 1037,1603 1050,1610
  rectangle net PGND: 1046,1602 1057,1614
  rectangle net PGND: 1824,2078 2135,2455
  rectangle net PGND: 2118,2075 2393,2133
  rectangle net PGND: 2402,1784 2455,2042
  rectangle net PGND: 2332,2035 2394,2080
  rectangle net PGND: 2121,2118 2196,2162
  rectangle net PGND: 2367,1996 2422,2043
  region net PGND: 2406,1959 2431,1984 2323,2092 2298,2067
  region net PGND: 2307.5,2057.5 2322,2072 2305.5,2088.5 2291,2074
  region net PGND: 2194,2096 2229.5,2131.5 2136,2225 2100.5,2189.5
  region net GND: 2254.5,347.5 2267,360 2243.5,383.5 2231,371
  region net GND: 2234,337 2251,354 2221,384 2204,367
  region net GND: 2130.5,242.5 2231,343 2189.5,384.5 2089,284
  region net GND: 2131.5,235.5 2159,263 2153.5,268.5 2126,241
  region net GND: 2136.5,231.5 2153,248 2143.5,257.5 2127,241
  region net GND: 1658,1204 1889,1435 1868,1456 1637,1225
  region net GND: 1710,1197 1887,1374 1845,1416 1668,1239
  region net GND: 2164,1193 2188.5,1217.5 2161,1245 2136.5,1220.5
  region net PGND: 2121,2228 2152,2259 2140,2271 2109,2240
  region net PGND: 2134,2216 2159,2241 2145,2255 2120,2230
  region net PGND: 2138,2194 2168.5,2224.5 2153,2240 2122.5,2209.5
  region net PGND: 2228,2103 2255.5,2130.5 2164,2222 2136.5,2194.5
  region net PGND: 2247,2114 2265,2132 2235,2162 2217,2144
  region net PGND: 2262,2123 2272.5,2133.5 2255,2151 2244.5,2140.5
  region net PGND: 365,2244 380.5,2259.5 364,2276 348.5,2260.5
  region net PGND: 373,2212 389,2228 358,2259 342,2243
  region net PGND: 365,2190 384,2209 351,2242 332,2223
  region net PGND: 276,2093 371,2188 338,2221 243,2126
  region net PGND: 245,2118 281,2154 272,2163 236,2127
  region net PGND: 236,2119 263.5,2146.5 255,2155 227.5,2127.5
  region net PGND: 236,2127 251.5,2142.5 244,2150 228.5,2134.5
  region net GND: 1682.5,554.5 1805,677 1599.5,882.5 1477,760
  region net GND: 1756.18,554.82 1805,603.64 1750.82,657.82 1702,609
  rectangle net GND: 1478,759 1803,1225
  rectangle net GND: 1685,606 1805,769
  rectangle net GND: 1683,554.88 1752,597
  rectangle net NetC35_2: 1915.3,606 2145,656.42
  rectangle net NetC35_2: 2136,602 2234.21,625.92
  rectangle net NetC35_2: 2140,621 2152,646
  rectangle net NetC35_2: 2150,619 2159,639
  rectangle net NetC35_2: 2157,621 2168,632
  rectangle net NetC35_2: 1829,605 1907,671
  rectangle net NetC35_2: 1904,602 1919,659
  rectangle net NetC35_2: 1827,670 1903,734
  rectangle net NetC35_2: 1825,719 1866,863
  rectangle net NetC35_2: 1859,838 1873,863
  rectangle net NetC35_2: 1864,729 1871,746
  rectangle net NetC35_2: 1869,730 1877,742
  rectangle net NetJP5_2: 1928,675 1976,733
  rectangle net NetJP5_2: 1970,671 2226,703
  rectangle net NetJP5_2: 2178,644 2227,679
  rectangle net NetJP5_2: 2159,666 2175,682
  rectangle net NetJP5_2: 2166,654 2189,671
  rectangle net GND: 1976,783 2135,898
  rectangle net GND: 1985,893 2130,907
  rectangle net GND: 2120,832 2223,863
  rectangle net GND: 2007,729 2225,745
  rectangle net GND: 2010,730 2154,784
  rectangle net GND: 2129,779 2155.47,839
  rectangle net NetJP5_2: 1919,843 1953,863
  rectangle net NetJP5_2: 1945,838 1953,847
  rectangle net NetC34_2: 1887,809 1909,828
  rectangle net GND: 1966,1180 2155,1294
  rectangle net NetJP1_2: 2177,1085 2257,1176
  rectangle net NetJP1_2: 1975,1086 2184,1135
  rectangle net GND: 1958,1157 2133,1198
  rectangle net GND: 2152,1197 2254,1223
  rectangle net GND: 1744,1153 1971,1294
  rectangle net GND: 1859,1280 1887,1453
  rectangle net GND: 1846,1388 1872,1411
  rectangle net GND: 1793,1261 1874,1353
  rectangle net GND: 1885,1288 1895,1301
  rectangle net GND: 1672,1199 1795,1239
  rectangle net GND: 1788,1000 1955,1162
  rectangle net GND: 1897,949 1955,1006
  rectangle net GND: 1801,992 1812,1001
  rectangle net GND: 1890,991 1903,1002
  rectangle net GND: 1897,914 1921,948
  rectangle net GND: 1912,938 1947,955
  rectangle net GND: 1918,921 1930,941
  rectangle net GND: 1928,931 1939,941
  rectangle net NetR33_1: 1975,930 2025,1065
  rectangle net NetJP3_2: 2056,930 2126,1067
  rectangle net NetC35_2: 2146,1006 2252,1065
  rectangle net NetC35_2: 2176,976 2253,1016
  rectangle net NetJP3_2: 2172,889 2225,945
  rectangle net NetJP3_2: 2122,925 2183,957
  rectangle net NetC34_2: 1887,759 1935,821
  rectangle net GND: 1979,755 2020,785
  rectangle net GND: 2000,734 2020,757
  rectangle net GND: 1986,747 2007,756
  rectangle net GND: 1993,739 2004,749
  region net NetR33_1: 1931,896 1975,940 1975,940 1931,896
  region net NetR33_1: 1974,929 1980,935 1975,940 1969,934
  region net GND: 1987,888 1995.5,896.5 1987,905 1978.5,896.5
  region net GND: 1907,935 1922.5,950.5 1909,964 1893.5,948.5
  region net GND: 2153,842 2170.36,859.36 2136.86,892.85 2119.51,875.49
  region net GND: 2145,801 2177,833 2164,846 2132,814
  region net NetJP3_2: 2171,891 2199,919 2165,953 2137,925
  region net NetJP3_2: 2147,930 2169.5,952.5 2128,994 2105.5,971.5
  region net NetC35_2: 2174,978 2196,1000 2170,1026 2148,1004
  region net NetC35_2: 2244.5,959.5 2257,972 2241.5,987.5 2229,975
  region net NetC35_2: 2251,954 2258,961 2250,969 2243,962
  region net GND: 2163,733 2177.5,747.5 2155.47,769.53 2140.97,755.03
  region net NetJP5_2: 1986,689 2001,704 1976,729 1961,714
  region net NetJP1_2: 2152,1107 2199,1154 2179,1174 2132,1127
  region net GND: 2130.36,1153.64 2155,1178.28 2132.64,1200.64 2108,1176
  region net GND: 2257,1193 2268.5,1204.5 2257,1216 2245.5,1204.5
  region net GND: 2267,1194 2270.5,1197.5 2264,1204 2260.5,1200.5
  rectangle net GND: 334,329 376,369
  rectangle net NetC27_2: 1758,1639 1825,1777
  rectangle net NetC27_2: 1656,1683 1682,1694
  rectangle net NetC27_2: 1665,1671 1682,1686
  rectangle net NetC27_2: 1685,1654 1708,1663
  rectangle net NetC27_2: 1690,1644 1708,1657
  rectangle net PGND: 1685,1527 1823,1615
  rectangle net LODRV: 1086,1592 1184,1697
  rectangle net LODRV: 1072,1652 1099,1694
  rectangle net PGND: 1002,1908 1052,1924
  rectangle net PGND: 996,1883 1050,1910
  rectangle net PGND: 986,1881 1005,1902
  rectangle net PGND: 983,1757 1052,1894
  rectangle net PGND: 1049,1712 1065,1760
  rectangle net PGND: 1062,1714 1120,1758
  rectangle net PGND: 1099,1717 1183,1744
  rectangle net PGND: 1118,1741 1127,1750
  rectangle net GND: 997,1182 1119,1303
  rectangle net ACOK: 568,293 615,371
  rectangle net ACOK: 562,329 573,342
  rectangle net ACOK: 472,339 556,360
  rectangle net NetD3_2: 401,300 540,322
  rectangle net NetD3_2: 539,296 548,312
  rectangle net NetD3_2: 537,240 553,253
  rectangle net NetD3_2: 515,216 545,246.79
  rectangle net GND: 392,375 460,457
  rectangle net GND: 363,338 444,378
  rectangle net GND: 439,367 453,377
  rectangle net GND: 360,321 383,341
  rectangle net GND: 427,107 439,121
  rectangle net GND: 367,104 433,280
  rectangle net GND: 427,255 499,280.41
  rectangle net GND: 411,216 495,258
  rectangle net GND: 431,207 441,217
  rectangle net GND: 364,274 380,310
  rectangle net GND: 377,276 388,285
  rectangle net GND: 350,261 365,295
  rectangle net GND: 341,265 355,284
  text "Bottom Layer" at 577,-858.49 h60

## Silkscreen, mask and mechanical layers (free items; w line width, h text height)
Top Overlay:
  lines w10: 351,580 351,628 ; 636,83 636,131 ; 650,580 650,628 ; 950,580 950,628 ; 988,80 988,128 ; 1250,580 1250,628 ; 1551,580 1551,628 ; 1850,580 1850,628 ; 2102,625 2135,578
  text "PWR583" at 236,2082 h60
  text "SYS" at 2148,2018 h50
  text "Rev B" at 236,1996 h60
  text "GND" at 1994,1620 h50
  text "BAT" at 2276,1337 h50
  text "VIN" at 88,1263 h50
  text "GND" at 1641,792 h35
  text "GND" at 103,747 h50
  text "ACDRV" at 275,653 h35
  text "ACOK" at 579,652 h35
  text "IDCHG" at 868,645 h35
  text "/PROCHOT" at 1141,644 h35
  text "TB_STAT" at 1444,643 h35
  text "VCC" at 2045,640 h35
  text "BATDRV" at 1773,639 h35
  text "PMON" at 1037,582 h35
  text "/BATPRES" at 1264,582 h35
  text "CMSRC" at 113,581 h35
  text "ACDET" at 427,581 h35
  text "IADP" at 741,580 h35
  text "ILIM" at 1643,580 h35
  text "REGN" at 1936,580 h35
  text "GND" at 2377,493 h35
  text "GND" at 1083,290 h40
  text "SDA" at 1223,290 h40
  text "SCL" at 1363,290 h40
  text "3V3" at 1493,290 h40
  text "CMPI" at 1633,290 h40
  text "CMPO" at 1793,290 h40
  text "ACOK" at 444,94 h35
  text "/BATPRES" at 694,90 h35
  text "/PROCHOT" at 541,30 h35
  text "TB_STAT" at 839,29 h35
  text "Top Overlay" at 577,-858.49 h60
Bottom Overlay:
  lines w10: 1935,1016 1965,986
  text "Bottom Overlay" at 577,-858.49 h60
Top Paste:
  text "Top Paste" at 577,-858.49 h60
Bottom Paste:
  text "Bottom Paste" at 577,-858.49 h60
Top Solder:
  text "Top Solder" at 577,-858.49 h60
Bottom Solder:
  text "Bottom Solder" at 577,-858.49 h60
Drill Guide:
  text "Drill Guide" at 577,-858.49 h60
M1 Board Outline:
  the board outline again, w10
  text "Board Outline" at 577,-858.49 h60
M2 Board Dimensions:
  rectangle: 124.5,-410.5 499.5,-285.5
  rectangle: -0.5,-285.5 124.5,-160.5
  lines w7: -0.5,-285.5 999.5,-285.5 ; 124.5,-410.5 124.5,-160.5 ; 249.5,-410.5 249.5,-160.5 ; 499.5,-410.5 499.5,-160.5 ; 749.5,-410.5 749.5,-160.5 ; -0.5,-410.5 -0.5,-160.5 999.5,-160.5 999.5,-410.5 -0.5,-410.5
  lines w10: -0.5,-475.5 -0.5,-455.5 ; 59.5,-485.5 -0.5,-465.5 ; 59.5,-445.5 -0.5,-465.5 ; 223.58,-465.5 -0.5,-465.5 ; 775.42,-465.5 999.5,-465.5 ; 939.5,-485.5 999.5,-465.5 ; 939.5,-445.5 999.5,-465.5 ; 999.5,-475.5 999.5,-455.5
  text "1000 (mil)" at 233.58,-501.49 h60
  text "Board Dimensions" at 577,-858.49 h60
M3 3D STEP Top:
  text "STEP Top" at 577,-858.49 h60
M4 3D STEP Bottom:
  text "STEP Bottom" at 577,-858.49 h60
M5 Assembly Top:
  lines w7: 5139,110.5 6264,110.5 ; 5139,233 6261.5,233 ; 5454,-9.5 5454,353 ; 5839,-9.5 5139,-9.5 ; 5839,353 5139,353 ; 5139,-9.5 5139,353 ; 5139,-9.5 6264,-9.5 6264,353 5139,353
  lines w10: -292,-930.17 6308,-930.17 ; -292,-726.83 6310,-726.83 ; -292,-523.5 -292,-1133.5 3713,-1133.5 6310,-1133.5 6310,-523.5 -291.5,-523.5 -291.5,-1133.5 1284,-1133.5 ; 2173,-1133.5 2173,-523.5 ; 3440,-726.83 3440,-523.5 ; 4280,-726.83 4280,-523.5 ; 4902,-1140 4902,-937.17
  text "TABLE 1" at 5526.5,388 h35
  text "Variant" at 5164,278 h35
  text "Label text" at 5599,278 h35
  text "001" at 5231.5,158 h35
  text "bq24780S EVM" at 5509,155.5 h35
  text "002" at 5231.5,33 h35
  text "COMPONENTS MARKED 'DNP' SHOULD NOT BE POPULATED." at 1153.5,-318.5 h60
  text "ASSEMBLY VARIANT:" at 1153,-434 h60
  text ".VariantName" at 2189,-434 h60
  text "PCB VIEWED FROM TOP SIDE" at -228.5,-655.67 h60
  text "BOARD #:" at 2248,-655.67 h60
  text "PWR583" at 2793.5,-655.67 h60
  text "REV:" at 3638,-655.67 h60
  text "B" at 3929.5,-655.67 h60
  text "SVN REV:" at 4476,-655.67 h60
  text "IGNORE ->" at -228.5,-858.49 h60
  text "PLOT NAME =" at -228.5,-1064.34 h60
  text "GENERATED    :" at 2250,-1064.34 h60
  text "07/08/2014" at 3119.5,-1064.34 h60
  text "TEXAS INSTRUMENTS" at 5113,-1064.34 h60
M6 Assembly Bottom:
  lines w10: -292.5,-727.33 6309.5,-727.33 ; -290.5,-930.67 6309.5,-930.67 ; 1115.5,-1140.5 1115.5,-937.67 ; 1737.5,-727.33 1737.5,-524 ; 2577.5,-727.33 2577.5,-524 ; 3844.5,-1134 3844.5,-524 ; 4733.5,-1134 6309,-1134 6309,-524 -292.5,-524 -292.5,-1134 2304.5,-1134 6309.5,-1134 6309.5,-524
  text "COMPONENTS MARKED 'DNP' SHOULD NOT BE POPULATED." at 6102,-318 h60
  text ".VariantName" at 5058,-434 h60
  text "ASSEMBLY VARIANT:" at 6097,-434 h60
  text "SVN REV:" at 1541.5,-656.17 h60
  text "B" at 2088,-656.17 h60
  text "REV:" at 2379.5,-656.17 h60
  text "PWR583" at 3224,-656.17 h60
  text "BOARD #:" at 3769.5,-656.17 h60
  text "PCB VIEWED FROM BOTTOM SIDE" at 6246,-656.17 h60
  text "IGNORE ->" at 2547.85,-858.49 h60
  text "TEXAS INSTRUMENTS" at 904.5,-1064.84 h60
  text "07/08/2014" at 2898,-1064.84 h60
  text "GENERATED    :" at 3767.5,-1064.84 h60
  text "PLOT NAME =" at 6246,-1064.84 h60
M9 Title Sheet:
  drawing of 57 lines, arcs and shapes, not listed
  text "1" at 739.84,8036.5 h70
  text "2" at 3235.5,8036.5 h70
  text "3" at 5724.84,8036.5 h70
  text "4" at 8231.51,8036.5 h70
  text "5" at 10730.5,8036.5 h70
  text "6" at 13235.5,8036.5 h70
  text "A" at -416.5,6893.5 h70
  text "A" at 14383.5,6893.5 h70
  text "B" at -416.5,4513.5 h70
  text "B" at 14383.5,4513.5 h70
  text "C" at -416.5,2138.5 h70
  text "C" at 14383.5,2138.5 h70
  text "PROJECT TITLE:" at 11343.5,277.5 h45
  text "bq24780EVM" at 11393.5,144.17 h70
  text "DESIGNED FOR:" at 11343.5,-23.5 h45
  text "Public Release" at 11388.5,-148.83 h70
  text "D" at -416.5,-231.5 h70
  text "D" at 14383.5,-231.5 h70
  text "FILE NAME:" at 11343.5,-323.5 h45
  text "PWR583ReV A.PCBDOC" at 11393.5,-443.5 h70
  text "Texas Instruments (TI) and/or its licensors do not warrant the accuracy or completeness of this specification" at 6374,-605.34 h45
  text "ENGINEER:" at 11343.5,-613.5 h45
  text "LAYOUT BY:" at 12848.5,-613.5 h45
  text "or any information contained therein. TI and/or its licensors do not warrant that this design will meet" at 6329.01,-718 h45
  text "Jing Ye" at 11379,-759.49 h70
  text "Alex Ji" at 12899,-768.49 h70
  text "the specifications, will be suitable for your application or fit for any particular purpose, or will operate in" at 6329.01,-830.67 h45
  text "Title Sheet" at 577,-858.49 h60
  text "ALTIUM DESIGNER VERSION:" at 12848.5,-923.5 h45
  text "an implementation. TI and/or its licensors do not warrant that the design is production worthy. You should" at 6329.01,-943.33 h45
  text "completely validate and test your design implementation to confirm the system functionality for your application." at 6374,-1056 h45
  text "1" at 739.84,-1263.5 h70
  text "2" at 3235.5,-1263.5 h70
  text "3" at 5724.84,-1263.5 h70
  text "4" at 8231.51,-1263.5 h70
  text "5" at 10730.5,-1263.5 h70
  text "6" at 13235.5,-1263.5 h70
